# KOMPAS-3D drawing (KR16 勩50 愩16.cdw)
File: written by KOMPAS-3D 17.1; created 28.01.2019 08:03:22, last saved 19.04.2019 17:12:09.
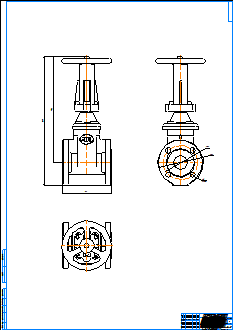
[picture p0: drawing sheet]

Sheet 1: A0, portrait

Title block, sheet 1: name: KR16 Ду50 Ру16; material: Внимание! Данный продукт является объектом авторского права ООО «Торговый Дом АДЛ». / Запрещается изменение, копирование, распространение / (в том числе путем копирования на другие сайты и ресурсы в Интернете) / или любое иное использование информации и объектов без предварительного / согласия правообладателя (ООО «Торговый Дом АДЛ»).; sheets: 1; organisation: ООО "Торговый дом АДЛ"; sheet format: A0; stored path: \\adlc.lan\data\АДЛ_ПКД\3D-модели\ADL production\Клиновые задвижки серии KR ГРАНАР\Клиновые задвижки KR16\Со штурвалом\KOMPAS 2D\KR16 Ду50.cdw

Views: Вид 1, Проекционный вид 2, Проекционный вид 3
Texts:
  user
Dimensions and other numbers on the sheet: 178; 466,5; 384; 125; 165; 19; 4 отв.; 1:1; 1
